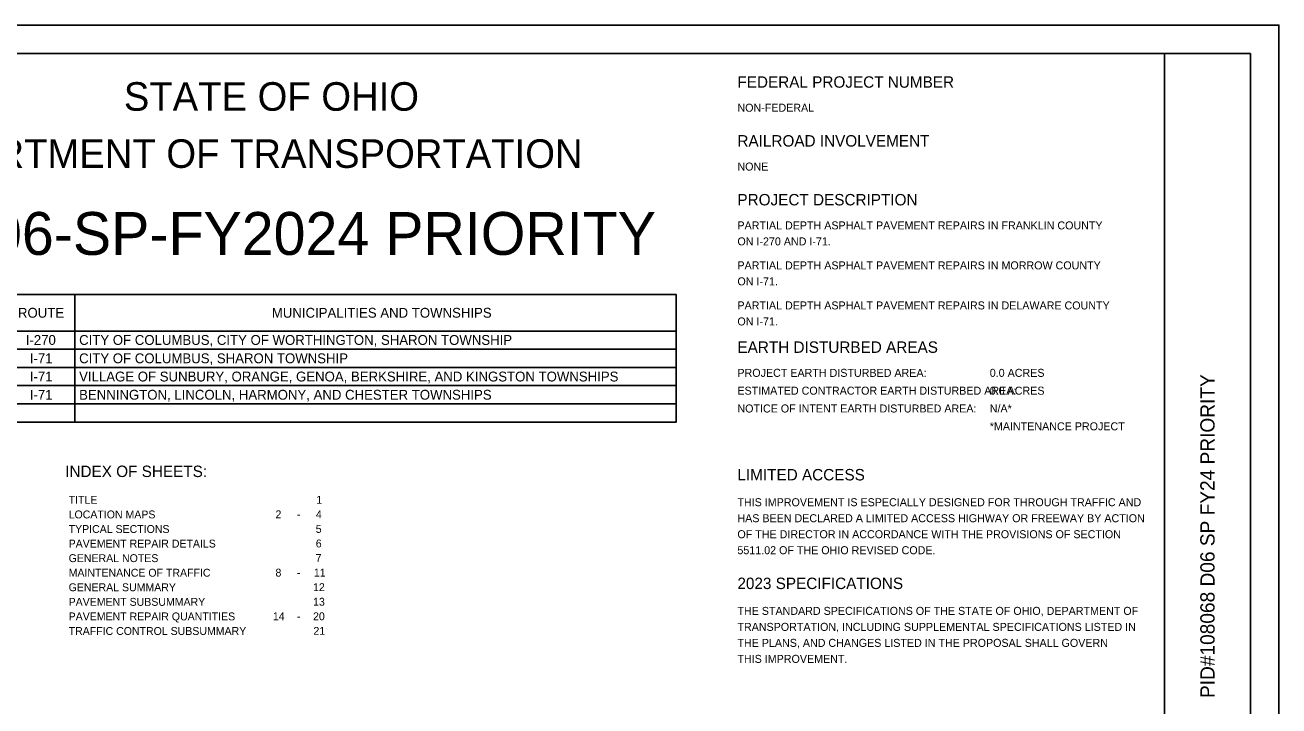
# Model space of a CAD drawing. Extents: x 0 to 34, y 0 to 22.
# Drawn here: x 12.07 to 34, y 10.08 to 22 of the extents above; entities that cross this region are included whole.
import ezdxf

# ---------------------------------------------------------------- set-up
doc = ezdxf.new("R2010")
doc.units = 0
for name, color, linetype in [('Default', 7, 'Continuous'), ('SH_Border', 7, 'Continuous'), ('SH_Cut_Line', 7, 'Continuous'), ('SH_Data', 7, 'Continuous'), ('SH_Text', 7, 'Continuous')]:
    doc.layers.add(name, color=color, linetype=linetype)

msp = doc.modelspace()

# ---------------------------------------------------------------- linework, layer by layer
at = {"layer": 'Default'}
for p, q in [((10.182, 17.282), (23.457, 17.282)), ((12.938, 17.282), (12.938, 15.051)), ((23.457, 17.282), (23.457, 15.051)), ((10.182, 16.644), (23.457, 16.644)), ((10.182, 16.326), (23.457, 16.326)), ((10.182, 16.007), (23.457, 16.007)), ((10.182, 15.688), (23.457, 15.688)), ((10.182, 15.369), (23.457, 15.369)), ((10.182, 15.051), (23.457, 15.051))]:
    msp.add_line(p, q, dxfattribs=at)
for points in [[(11.719, 17.282), (12.938, 17.282), (12.938, 16.644), (11.719, 16.644)], [(12.938, 17.282), (23.457, 17.282), (23.457, 16.644), (12.938, 16.644)], [(11.719, 16.644), (12.938, 16.644), (12.938, 16.326), (11.719, 16.326)], [(12.938, 16.644), (23.457, 16.644), (23.457, 16.326), (12.938, 16.326)], [(11.719, 16.326), (12.938, 16.326), (12.938, 16.007), (11.719, 16.007)], [(12.938, 16.326), (23.457, 16.326), (23.457, 16.007), (12.938, 16.007)], [(11.719, 16.007), (12.938, 16.007), (12.938, 15.688), (11.719, 15.688)], [(12.938, 16.007), (23.457, 16.007), (23.457, 15.688), (12.938, 15.688)], [(11.719, 15.688), (12.938, 15.688), (12.938, 15.369), (11.719, 15.369)], [(12.938, 15.688), (23.457, 15.688), (23.457, 15.369), (12.938, 15.369)], [(11.719, 15.369), (12.938, 15.369), (12.938, 15.051), (11.719, 15.051)], [(12.938, 15.369), (23.457, 15.369), (23.457, 15.051), (12.938, 15.051)]]:
    msp.add_lwpolyline(points, close=True, dxfattribs=at)
at = {"layer": 'SH_Border'}
msp.add_line((32, 0.5), (32, 21.5), dxfattribs=at)
msp.add_lwpolyline([(1.5, 21.5), (33.5, 21.5), (33.5, 0.5), (1.5, 0.5)], close=True, dxfattribs=at)
at = {"layer": 'SH_Cut_Line'}
msp.add_lwpolyline([(0, 0), (34, 0), (34, 22), (0, 22)], close=True, dxfattribs=at)

# ---------------------------------------------------------------- texts
at = {"layer": 'Default'}
for s, height, p in [('ROUTE', 0.1725, (11.943, 16.877)), ('MUNICIPALITIES AND TOWNSHIPS', 0.1725, (16.384, 16.877)), ('I-270', 0.1725, (12.08, 16.401)), ('CITY OF COLUMBUS, CITY OF WORTHINGTON, SHARON TOWNSHIP', 0.1725, (13.013, 16.401)), ('I-71', 0.1725, (12.15, 16.08)), ('CITY OF COLUMBUS, SHARON TOWNSHIP', 0.1725, (13.013, 16.08)), ('I-71', 0.1725, (12.15, 15.761)), ('VILLAGE OF SUNBURY, ORANGE, GENOA, BERKSHIRE, AND KINGSTON TOWNSHIPS', 0.1725, (13.013, 15.761)), ('I-71', 0.1725, (12.15, 15.442)), ('BENNINGTON, LINCOLN, HARMONY, AND CHESTER TOWNSHIPS', 0.1725, (13.013, 15.442)), ('TITLE', 0.138, (12.83, 13.619)), ('1', 0.138, (17.161, 13.621)), ('LOCATION MAPS', 0.138, (12.83, 13.364)), ('2', 0.138, (16.448, 13.366)), ('-', 0.138, (16.821, 13.366)), ('4', 0.138, (17.155, 13.366)), ('TYPICAL SECTIONS', 0.138, (12.83, 13.109)), ('5', 0.138, (17.152, 13.111)), ('PAVEMENT REPAIR DETAILS', 0.138, (12.83, 12.854)), ('6', 0.138, (17.153, 12.856)), ('GENERAL NOTES', 0.138, (12.83, 12.599)), ('7', 0.138, (17.15, 12.601)), ('MAINTENANCE OF TRAFFIC', 0.138, (12.83, 12.344)), ('8', 0.138, (16.448, 12.346)), ('-', 0.138, (16.821, 12.346)), ('11', 0.138, (17.119, 12.346)), ('GENERAL SUMMARY', 0.138, (12.83, 12.089)), ('12', 0.138, (17.105, 12.091)), ('PAVEMENT SUBSUMMARY', 0.138, (12.83, 11.834)), ('13', 0.138, (17.106, 11.836)), ('PAVEMENT REPAIR QUANTITIES', 0.138, (12.83, 11.579)), ('14', 0.138, (16.402, 11.581)), ('-', 0.138, (16.821, 11.581)), ('20', 0.138, (17.105, 11.581)), ('TRAFFIC CONTROL SUBSUMMARY', 0.138, (12.83, 11.324)), ('21', 0.138, (17.112, 11.326))]:
    msp.add_text(s, height=height, dxfattribs=at).set_placement(p)
at = {"layer": 'SH_Data'}
msp.add_text('PID#108068 D06 SP FY24 PRIORITY', height=0.25, rotation=90, dxfattribs=at).set_placement((32.875, 10.22))
at = {"layer": 'SH_Text'}
for s, height, p in [('FEDERAL PROJECT NUMBER', 0.2, (24.528, 20.903)), ('STATE OF OHIO', 0.5, (13.795, 20.5)), ('NON-FEDERAL', 0.14, (24.528, 20.483)), ('DEPARTMENT OF TRANSPORTATION', 0.5, (9.747, 19.5)), ('RAILROAD INVOLVEMENT', 0.2, (24.528, 19.873)), ('NONE', 0.14, (24.528, 19.453)), ('PROJECT DESCRIPTION', 0.2, (24.528, 18.843)), ('D06-SP-FY2024 PRIORITY', 0.75, (10.73, 17.977)), ('PARTIAL DEPTH ASPHALT PAVEMENT REPAIRS IN FRANKLIN COUNTY', 0.14, (24.528, 18.423)), ('ON I-270 AND I-71.', 0.14, (24.528, 18.143)), ('PARTIAL DEPTH ASPHALT PAVEMENT REPAIRS IN MORROW COUNTY', 0.14, (24.528, 17.723)), ('ON I-71.', 0.14, (24.528, 17.443)), ('PARTIAL DEPTH ASPHALT PAVEMENT REPAIRS IN DELAWARE COUNTY', 0.14, (24.528, 17.022)), ('ON I-71.', 0.14, (24.528, 16.742)), ('EARTH DISTURBED AREAS', 0.2, (24.528, 16.262)), ('PROJECT EARTH DISTURBED AREA:', 0.14, (24.528, 15.842)), ('0.0 ACRES', 0.14, (28.942, 15.842)), ('ESTIMATED CONTRACTOR EARTH DISTURBED AREA:', 0.14, (24.528, 15.53)), ('0.0 ACRES', 0.14, (28.942, 15.53)), ('NOTICE OF INTENT EARTH DISTURBED AREA:', 0.14, (24.528, 15.218)), ('N/A*', 0.14, (28.942, 15.218)), ('*MAINTENANCE PROJECT', 0.14, (28.942, 14.906)), ('INDEX OF SHEETS:', 0.2, (12.77, 14.088)), ('LIMITED ACCESS', 0.2, (24.528, 14.029)), ('THIS IMPROVEMENT IS ESPECIALLY DESIGNED FOR THROUGH TRAFFIC AND', 0.14, (24.528, 13.577)), ('HAS BEEN DECLARED A LIMITED ACCESS HIGHWAY OR FREEWAY BY ACTION', 0.14, (24.528, 13.297)), ('OF THE DIRECTOR IN ACCORDANCE WITH THE PROVISIONS OF SECTION', 0.14, (24.528, 13.017)), ('5511.02 OF THE OHIO REVISED CODE.', 0.14, (24.528, 12.737)), ('2023 SPECIFICATIONS', 0.2, (24.528, 12.127)), ('THE STANDARD SPECIFICATIONS OF THE STATE OF OHIO, DEPARTMENT OF', 0.14, (24.528, 11.675)), ('TRANSPORTATION, INCLUDING SUPPLEMENTAL SPECIFICATIONS LISTED IN', 0.14, (24.528, 11.395)), ('THE PLANS, AND CHANGES LISTED IN THE PROPOSAL SHALL GOVERN', 0.14, (24.528, 11.115)), ('THIS IMPROVEMENT.', 0.14, (24.528, 10.835))]:
    msp.add_text(s, height=height, dxfattribs=at).set_placement(p)

doc.saveas('drawing.dxf')
